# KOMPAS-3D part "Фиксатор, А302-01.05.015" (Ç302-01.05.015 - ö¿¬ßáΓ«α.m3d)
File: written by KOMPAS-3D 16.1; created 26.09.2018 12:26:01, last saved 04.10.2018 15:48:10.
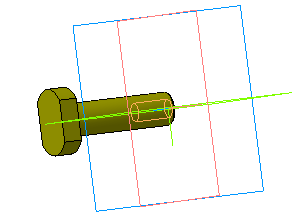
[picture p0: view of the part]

Document properties: Автор: Милов; Полное имя файла: D:\Мембранные насосы\Мембранный электропривод\А302-00.00.000 - ASTRA-302 (МЭ200)\3Д ПВХ\А302-01.05.015 - Фиксатор.m3d

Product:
- Part/product: Фиксатор  | designation А302-01.05.015
    Материал: Сталь 40  ГОСТ 1050-2013 (density 7820 kg/m3)
    Масса: 0.0222771
    Раздел спецификации: Детали
    Форматы листов документа: A4
    source file: А302-01.05.015 - Фиксатор.cdw

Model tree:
1. Эскиз:1
2. Операция вращения:1
     Угол 1 = 360
3. Отверстие:1
     Глубина выреза = 12; Диаметр отверстия = 4.13397; Угол конуса торца = 118
4. M5
     Длина резьбы = 10; Шаг резьбы = 0.8; Номинальный диаметр резьбы = 5
5. Эскиз:2
6. Вырезать элемент выдавливания:1
     Расстояние 2 = 10; На расстояние 1 = 8
7. Фаска:3
     Угол = 45; Длина 1 = 1; Длина 2 = 1
8. Фаска:4  (labels: Сталь 40  ГОСТ 1050-2013; А302-01.05.015)
     Угол = 45; Длина 1 = 0.5; Длина 2 = 0.5

Referenced files in C:\Program Files\ASCON\KOMPAS-3D V16\Sys\Thread\: cil0_8724-2002 coarse.xml
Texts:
  Линейный размер с обрывом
